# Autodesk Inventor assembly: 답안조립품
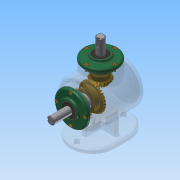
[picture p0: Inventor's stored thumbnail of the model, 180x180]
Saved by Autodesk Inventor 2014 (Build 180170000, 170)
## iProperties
Created: 2016-04
Part Number: 답안조립품
Document SubType Name: Assembly
Designer: 601-
Author: 601-
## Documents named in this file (14)
- C:\Users\601-\Desktop\460408V1007\답안조립품.iam
- C:\Users\601-\Desktop\460408V1007\본체.ipt
- C:\Users\601-\Desktop\460408V1007\메인 베벨기어.ipt
- C:\Users\601-\Desktop\460408V1007\메인 축.ipt
- 메인 축.ipt
- C:\Users\601-\Desktop\460408V1007\키 5x5.ipt
- C:\Users\601-\Desktop\460408V1007\베어링 6203.ipt
- C:\Users\601-\Desktop\460408V1007\오일실 17 32 8.ipt
- C:\Users\601-\Desktop\460408V1007\커버.ipt
- C:\Users\601-\Desktop\460408V1007\서브 베벨기어.ipt
- C:\Users\601-\Desktop\460408V1007\서브 축.ipt
- 서브 축.ipt
- C:\Users\601-\Desktop\460408V1007\키 4x4.ipt
- C:\Users\601-\Desktop\460408V1007\M4.ipt
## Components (8 placed, 1 different names)
1. M4:1
2. M4:3
3. M4:4
4. M4:5
5. M4:2
6. M4:6
7. M4:7
8. M4:8
